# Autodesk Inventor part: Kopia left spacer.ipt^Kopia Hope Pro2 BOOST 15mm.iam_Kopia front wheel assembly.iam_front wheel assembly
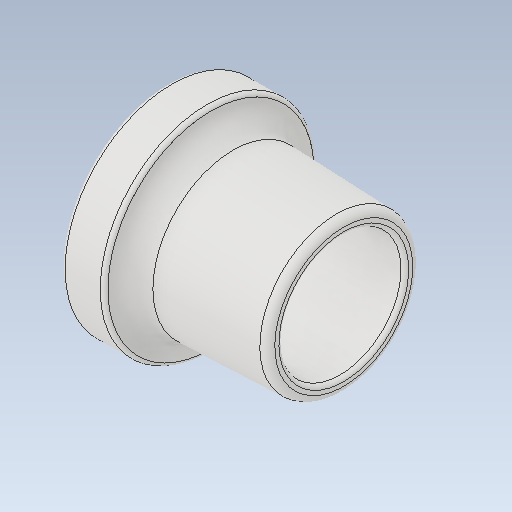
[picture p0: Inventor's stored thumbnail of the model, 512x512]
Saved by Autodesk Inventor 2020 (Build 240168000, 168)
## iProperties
Created: 2017-09
Part Number: Kopia left spacer.ipt^Kopia Hope Pro2 BOOST 15mm.iam_Kopia front wheel assembly.iam_front wheel assembly
Material: Ogólny
Document SubType Name: Modeling
Designer: Tomasz
Density: 1 g/cm^3
Appearance: Domyślna
Sending System: SolidWorks 2017
Last Author: Tomasz
Last Saved: 2017-09-11
Author: Tomasz
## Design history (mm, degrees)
feature "left spacer.ipt"
node "Bryła1"
